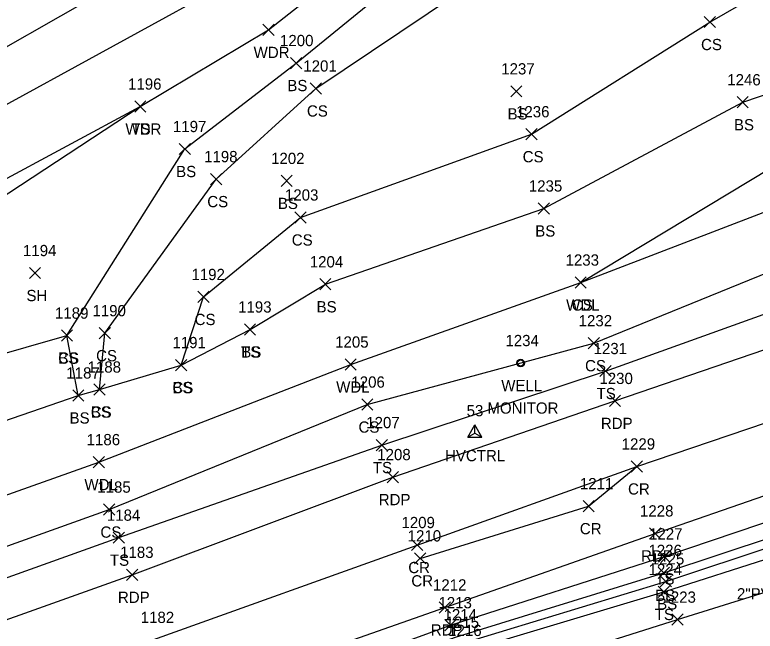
# Model space of a CAD drawing. Extents: x 1443064 to 1445163, y 544063 to 544655.
# Drawn here: x 1443332.1 to 1443463.7, y 544192.7 to 544302.3 of the extents above; entities that cross this region are included whole.
import ezdxf

# ---------------------------------------------------------------- set-up
doc = ezdxf.new("R2010")
doc.units = 0
for name, color, linetype in [('C_A', 7, 'Continuous'), ('C_I', 7, 'Continuous'), ('CPSM', 7, 'Continuous'), ('L_A', 7, 'Continuous'), ('L_C', 7, 'Continuous'), ('L_I', 7, 'Continuous'), ('L_TIC', 7, 'Continuous'), ('LAWA', 7, 'Continuous'), ('LAWE', 7, 'Continuous'), ('LELB', 7, 'Continuous'), ('LFNC', 7, 'Continuous'), ('P_A', 7, 'Continuous'), ('P_I', 7, 'Continuous'), ('P_TIC', 7, 'Continuous'), ('PET', 7, 'Continuous'), ('PRC', 7, 'Continuous'), ('U_A', 7, 'Continuous'), ('U_C', 7, 'Continuous'), ('U_I', 7, 'Continuous'), ('UWW', 7, 'Continuous')]:
    doc.layers.add(name, color=color, linetype=linetype)

msp = doc.modelspace()

# ---------------------------------------------------------------- linework, layer by layer
at = {"layer": 'CPSM'}
for p, q in [((1443412.62, 544227.22), (1443413.87, 544229.39)), ((1443415.12, 544227.22), (1443413.87, 544229.39)), ((1443413.87, 544227.94), (1443413.87, 544229.39)), ((1443412.62, 544227.22), (1443413.87, 544227.94)), ((1443412.62, 544227.22), (1443415.12, 544227.22)), ((1443413.87, 544227.94), (1443413.87, 544227.94)), ((1443413.87, 544227.94), (1443415.12, 544227.22))]:
    msp.add_line(p, q, dxfattribs=at)
at = {"layer": 'L_TIC'}
for points in [[(1443454.64, 544300.02), (1443456.64, 544302.02)], [(1443456.64, 544300.02), (1443454.64, 544302.02)], [(1443376.17, 544298.62), (1443378.17, 544300.62)], [(1443378.17, 544298.62), (1443376.17, 544300.62)], [(1443381.08, 544292.73), (1443383.08, 544294.73)], [(1443383.08, 544292.73), (1443381.08, 544294.73)], [(1443384.57, 544288.21), (1443386.57, 544290.21)], [(1443386.57, 544288.21), (1443384.57, 544290.21)], [(1443420.24, 544287.7), (1443422.24, 544289.7)], [(1443422.24, 544287.7), (1443420.24, 544289.7)], [(1443460.49, 544285.76), (1443462.49, 544287.76)], [(1443462.49, 544285.76), (1443460.49, 544287.76)], [(1443353.38, 544285), (1443355.38, 544287)], [(1443355.38, 544285), (1443353.38, 544287)], [(1443353.38, 544285), (1443355.38, 544287)], [(1443355.38, 544285), (1443353.38, 544287)], [(1443422.93, 544280.08), (1443424.93, 544282.08)], [(1443424.93, 544280.08), (1443422.93, 544282.08)], [(1443361.31, 544277.45), (1443363.31, 544279.45)], [(1443363.31, 544277.45), (1443361.31, 544279.45)], [(1443366.85, 544272.1), (1443368.85, 544274.1)], [(1443368.85, 544272.1), (1443366.85, 544274.1)], [(1443379.4, 544271.78), (1443381.4, 544273.78)], [(1443381.4, 544271.78), (1443379.4, 544273.78)], [(1443425.15, 544266.88), (1443427.15, 544268.88)], [(1443427.15, 544266.88), (1443425.15, 544268.88)], [(1443381.87, 544265.28), (1443383.87, 544267.28)], [(1443383.87, 544265.28), (1443381.87, 544267.28)], [(1443334.65, 544255.4), (1443336.65, 544257.4)], [(1443336.65, 544255.4), (1443334.65, 544257.4)], [(1443386.28, 544253.4), (1443388.28, 544255.4)], [(1443388.28, 544253.4), (1443386.28, 544255.4)], [(1443431.68, 544253.71), (1443433.68, 544255.71)], [(1443433.68, 544253.71), (1443431.68, 544255.71)], [(1443431.68, 544253.71), (1443433.68, 544255.71)], [(1443433.68, 544253.71), (1443431.68, 544255.71)], [(1443364.6, 544251.15), (1443366.6, 544253.15)], [(1443366.6, 544251.15), (1443364.6, 544253.15)], [(1443347.08, 544244.71), (1443349.08, 544246.71)], [(1443349.08, 544244.71), (1443347.08, 544246.71)], [(1443347.08, 544244.71), (1443349.08, 544246.71)], [(1443349.08, 544244.71), (1443347.08, 544246.71)], [(1443372.89, 544245.37), (1443374.89, 544247.37)], [(1443374.89, 544245.37), (1443372.89, 544247.37)], [(1443372.89, 544245.37), (1443374.89, 544247.37)], [(1443374.89, 544245.37), (1443372.89, 544247.37)], [(1443340.34, 544244.28), (1443342.34, 544246.28)], [(1443342.34, 544244.28), (1443340.34, 544246.28)], [(1443340.34, 544244.28), (1443342.34, 544246.28)], [(1443342.34, 544244.28), (1443340.34, 544246.28)], [(1443434.02, 544242.93), (1443436.02, 544244.93)], [(1443436.02, 544242.93), (1443434.02, 544244.93)], [(1443360.65, 544239.04), (1443362.65, 544241.04)], [(1443362.65, 544239.04), (1443360.65, 544241.04)], [(1443360.65, 544239.04), (1443362.65, 544241.04)], [(1443362.65, 544239.04), (1443360.65, 544241.04)], [(1443390.79, 544239.14), (1443392.79, 544241.14)], [(1443392.79, 544239.14), (1443390.79, 544241.14)], [(1443436.1, 544237.98), (1443438.1, 544239.98)], [(1443438.1, 544237.98), (1443436.1, 544239.98)], [(1443346.13, 544234.69), (1443348.13, 544236.69)], [(1443348.13, 544234.69), (1443346.13, 544236.69)], [(1443346.13, 544234.69), (1443348.13, 544236.69)], [(1443348.13, 544234.69), (1443346.13, 544236.69)], [(1443342.36, 544233.64), (1443344.36, 544235.64)], [(1443344.36, 544233.64), (1443342.36, 544235.64)], [(1443342.36, 544233.64), (1443344.36, 544235.64)], [(1443344.36, 544233.64), (1443342.36, 544235.64)], [(1443393.74, 544232.02), (1443395.74, 544234.02)], [(1443395.74, 544232.02), (1443393.74, 544234.02)], [(1443396.32, 544224.82), (1443398.32, 544226.82)], [(1443398.32, 544224.82), (1443396.32, 544226.82)], [(1443346.02, 544221.79), (1443348.02, 544223.79)], [(1443348.02, 544221.79), (1443346.02, 544223.79)], [(1443347.85, 544213.35), (1443349.85, 544215.35)], [(1443349.85, 544213.35), (1443347.85, 544215.35)], [(1443349.56, 544208.36), (1443351.56, 544210.36)], [(1443351.56, 544208.36), (1443349.56, 544210.36)], [(1443446.54, 544205.03), (1443448.54, 544207.03)], [(1443448.54, 544205.03), (1443446.54, 544207.03)], [(1443446.48, 544202.1), (1443448.48, 544204.1)], [(1443448.48, 544202.1), (1443446.48, 544204.1)], [(1443446.84, 544200.59), (1443448.84, 544202.59)], [(1443448.84, 544200.59), (1443446.84, 544202.59)], [(1443446.45, 544198.71), (1443448.45, 544200.71)], [(1443448.45, 544198.71), (1443446.45, 544200.71)], [(1443448.91, 544193.79), (1443450.91, 544195.79)], [(1443450.91, 544193.79), (1443448.91, 544195.79)], [(1443408.52, 544192.8), (1443410.52, 544194.8)], [(1443410.52, 544192.8), (1443408.52, 544194.8)]]:
    msp.add_lwpolyline(points, dxfattribs=at)
at = {"layer": 'LAWA'}
for points in [[(1443328.33, 544272.01), (1443354.38, 544286), (1443377.17, 544299.62), (1443408.35, 544324.23), (1443444.34, 544348.07), (1443478.82, 544379), (1443505.14, 544393.05), (1443523.9, 544408.72), (1443558.4, 544420.46), (1443603.2, 544442.99), (1443623.82, 544449.76), (1443648.97, 544490.11)], [(1443161.29, 544157.23), (1443186.09, 544163.69), (1443194.34, 544166.63), (1443196.33, 544167.63), (1443201.36, 544168), (1443240.97, 544179.17), (1443262.42, 544188.86), (1443303.08, 544207.19), (1443347.02, 544222.79), (1443391.79, 544240.14), (1443432.68, 544254.71), (1443466.61, 544275.19), (1443493.21, 544282.75), (1443512.25, 544287.37), (1443549.07, 544304.36), (1443598.9, 544317.54), (1443643.36, 544329.59), (1443677.18, 544341.83), (1443688.03, 544341.71), (1443709.45, 544338.47), (1443741.32, 544354.61), (1443794.32, 544372.46), (1443818.98, 544380.86)]]:
    msp.add_lwpolyline(points, dxfattribs=at)
at = {"layer": 'LAWE'}
msp.add_lwpolyline([(1443627.73, 544516.96), (1443602.93, 544465.06), (1443560.09, 544445.87), (1443514.11, 544419.1), (1443476.33, 544389.4), (1443439.4, 544357.75), (1443402.97, 544339.11), (1443368.14, 544318.06), (1443323.16, 544292.42), (1443281.44, 544273.46), (1443240.37, 544261.14), (1443193.33, 544260.65), (1443164.34, 544237.83), (1443139.78, 544220.74), (1443138.28, 544217.17), (1443133.77, 544210.32), (1443100.97, 544202.05)], dxfattribs=at)
at = {"layer": 'LELB'}
for points in [[(1443630.6, 544513.66), (1443606.19, 544459.79), (1443563.47, 544440.26), (1443516.58, 544414.23), (1443479.57, 544386.27), (1443441.49, 544354.15), (1443406.03, 544333.57), (1443372.48, 544309.35), (1443326.54, 544284.19), (1443284.74, 544264.48), (1443242.9, 544256.57), (1443195.74, 544252.68), (1443182.88, 544237.49), (1443172.34, 544228.16)], [(1443348.08, 544245.71), (1443367.85, 544273.1), (1443385.57, 544289.21), (1443415.45, 544309.3), (1443446.5, 544327.39), (1443476.22, 544341.09), (1443487.16, 544364.37), (1443505.14, 544393.05)], [(1443343.36, 544234.64), (1443341.34, 544245.28), (1443362.31, 544278.45), (1443382.08, 544293.73), (1443410.77, 544317.09), (1443446.9, 544337.74), (1443471.29, 544351.11), (1443478.82, 544379)], [(1443073.59, 544128.34), (1443116.66, 544141.89), (1443162.8, 544149.75), (1443198.07, 544157.24), (1443242.5, 544173.41), (1443262.84, 544182.05), (1443307.11, 544199.46), (1443348.85, 544214.35), (1443394.74, 544233.02), (1443435.02, 544243.93), (1443473.16, 544259.47), (1443514.32, 544272.16), (1443555.56, 544285.54), (1443605.06, 544302.52), (1443644.56, 544313.72), (1443676.09, 544324.26), (1443689.45, 544326.75), (1443708.55, 544330.01), (1443714.07, 544333.45), (1443742.84, 544349.83), (1443793.92, 544368.99), (1443822.61, 544377.56)], [(1443074.67, 544122.4), (1443120.32, 544131.74), (1443165.11, 544143.77), (1443199.58, 544153.13), (1443245.24, 544167.88), (1443264.59, 544177.57), (1443308.86, 544194.48), (1443350.56, 544209.36), (1443397.32, 544225.82), (1443437.1, 544238.98), (1443476.53, 544253.14), (1443516.75, 544265.8), (1443558.95, 544280.95), (1443607.52, 544296.39), (1443646.45, 544306.32), (1443685.12, 544319.06), (1443714.26, 544329.16), (1443721.31, 544331.26), (1443744.28, 544345.57), (1443795.65, 544366.53), (1443822.61, 544377.56)], [(1443298.3, 544219.12), (1443343.36, 544234.64), (1443347.13, 544235.69), (1443361.65, 544240.04), (1443373.89, 544246.37), (1443387.28, 544254.4), (1443426.15, 544267.88), (1443461.49, 544286.76), (1443487.3, 544295.55), (1443508.64, 544301.52), (1443524.64, 544310.64), (1443543.83, 544318.46), (1443565.18, 544320.82), (1443579.86, 544324.28), (1443590.71, 544328.22), (1443606.37, 544329.69), (1443641.44, 544343.33), (1443674.4, 544354.73), (1443679.77, 544354.99), (1443682.99, 544355.5), (1443689.34, 544351.28), (1443707.83, 544344.95), (1443741.32, 544354.61)], [(1443361.65, 544240.04), (1443365.6, 544252.15), (1443382.87, 544266.28), (1443423.93, 544281.08), (1443455.64, 544301.02), (1443483.09, 544316.84), (1443502.95, 544323.75), (1443492.91, 544341.29), (1443492.61, 544354.67)], [(1443082.68, 544086.51), (1443130.13, 544099.67), (1443144.13, 544104.98), (1443172.72, 544113.76), (1443212.83, 544125.42), (1443253.97, 544138.87), (1443319.39, 544160.76), (1443361, 544176.06), (1443409.52, 544193.8), (1443447.54, 544206.03), (1443485.93, 544218.99), (1443527.17, 544233.73), (1443570.65, 544246.93), (1443621.44, 544264.66), (1443656.15, 544276.08), (1443695.78, 544288.38), (1443720.36, 544296.79), (1443749.28, 544306.83), (1443759.63, 544310.57), (1443806.78, 544328.14), (1443835.8, 544338.24)], [(1443319.92, 544153.98), (1443361.38, 544174.3), (1443410.41, 544191.66), (1443447.48, 544203.1), (1443486.62, 544216.08), (1443527.2, 544231.22), (1443571.34, 544244.18), (1443622.82, 544261.27), (1443656.98, 544272.97), (1443695.69, 544285.56), (1443722.38, 544294.2), (1443748.12, 544301.75), (1443761.69, 544309.21), (1443807.82, 544325.32), (1443837.04, 544335.82)], [(1443432.68, 544254.71), (1443470.23, 544269.11), (1443497.41, 544276.29), (1443512.42, 544282.49), (1443553.95, 544298.49)], [(1443347.34, 544164.94), (1443362.1, 544171.53), (1443410.79, 544190.32), (1443447.84, 544201.59), (1443487.26, 544214.65), (1443527.73, 544229.42), (1443571.89, 544241.52), (1443623.27, 544260), (1443657.62, 544270.44), (1443688.01, 544274.03), (1443701.05, 544275.03), (1443736.1, 544284.41), (1443746.14, 544291.27)], [(1443065.69, 544181.55), (1443109.31, 544188.89), (1443136.73, 544199.63), (1443157.94, 544207.35), (1443161.61, 544194.55), (1443179.72, 544186.99), (1443184.46, 544169.42), (1443186.09, 544163.69), (1443190.43, 544160.91), (1443201.88, 544165.55), (1443201.36, 544168), (1443198.62, 544178.69), (1443186.97, 544194.77), (1443179.33, 544201.28), (1443169.79, 544215.76), (1443186.02, 544215.66), (1443204.39, 544216.66), (1443224.03, 544235.31), (1443250.92, 544228.56), (1443292.51, 544245.42), (1443354.38, 544286)], [(1443261.77, 544197.6), (1443297.02, 544232.6), (1443341.34, 544245.28)], [(1443347.13, 544235.69), (1443348.08, 544245.71)], [(1443347.34, 544164.94), (1443362.66, 544168.7), (1443411.3, 544188.87), (1443447.45, 544199.71), (1443486.7, 544212.27), (1443529.19, 544224.77), (1443545.25, 544228.26), (1443571.88, 544240.98), (1443578.87, 544240.7)]]:
    msp.add_lwpolyline(points, dxfattribs=at)
at = {"layer": 'LFNC'}
msp.add_lwpolyline([(1443239.88, 544119.45), (1443278.62, 544130.94), (1443320.57, 544148.06), (1443338.13, 544157.08), (1443351.22, 544161.82), (1443363.5, 544166.21), (1443412.24, 544182.91), (1443449.91, 544194.79), (1443489.63, 544207.22), (1443534.54, 544218.89), (1443545.24, 544222.13), (1443555.28, 544222.99), (1443566.76, 544221.91), (1443584.49, 544223.6), (1443632.95, 544239.56), (1443668.35, 544248.03), (1443707.08, 544263.81), (1443742.56, 544273.31)], dxfattribs=at)
at = {"layer": 'P_TIC'}
for points in [[(1443437.78, 544232.67), (1443439.78, 544234.67)], [(1443439.78, 544232.67), (1443437.78, 544234.67)], [(1443441.67, 544221.02), (1443443.67, 544223.02)], [(1443443.67, 544221.02), (1443441.67, 544223.02)], [(1443441.67, 544221.02), (1443443.67, 544223.02)], [(1443443.67, 544221.02), (1443441.67, 544223.02)], [(1443398.28, 544219.13), (1443400.28, 544221.13)], [(1443400.28, 544219.13), (1443398.28, 544221.13)], [(1443433.1, 544213.96), (1443435.1, 544215.96)], [(1443435.1, 544213.96), (1443433.1, 544215.96)], [(1443444.92, 544209.12), (1443446.92, 544211.12)], [(1443446.92, 544209.12), (1443444.92, 544211.12)], [(1443402.59, 544207.05), (1443404.59, 544209.05)], [(1443404.59, 544207.05), (1443402.59, 544209.05)], [(1443403.14, 544204.68), (1443405.14, 544206.68)], [(1443405.14, 544204.68), (1443403.14, 544206.68)], [(1443351.92, 544201.76), (1443353.92, 544203.76)], [(1443353.92, 544201.76), (1443351.92, 544203.76)], [(1443407.54, 544195.96), (1443409.54, 544197.96)], [(1443409.54, 544195.96), (1443407.54, 544197.96)]]:
    msp.add_lwpolyline(points, dxfattribs=at)
at = {"layer": 'PET'}
for points in [[(1443075.39, 544117.71), (1443121.41, 544129.24), (1443165.99, 544140.07), (1443200.71, 544149.88), (1443246.42, 544165.39), (1443265.96, 544172.48), (1443311.2, 544187.88), (1443352.92, 544202.76), (1443399.28, 544220.13), (1443438.78, 544233.67), (1443478.75, 544247.35), (1443518.41, 544260.6), (1443561.23, 544274.05), (1443611.7, 544290.5), (1443646.84, 544301.68), (1443684.98, 544314.55), (1443724.57, 544327.54), (1443735.41, 544331.22), (1443748.81, 544336.36), (1443799.43, 544353.96), (1443827.31, 544364.14)], [(1443081.93, 544089.54), (1443128.67, 544104.01), (1443173.03, 544117.15), (1443209.23, 544128.71), (1443253.49, 544142.88), (1443273.3, 544149.07), (1443318.27, 544165.2), (1443359.78, 544179.84), (1443408.54, 544196.96), (1443445.92, 544210.12), (1443484.92, 544223.61), (1443525.67, 544237.02), (1443568.63, 544251.04), (1443620.57, 544267.93), (1443654.52, 544278.93), (1443694.69, 544292.43), (1443717.24, 544299.44), (1443752.8, 544310.97), (1443757.72, 544314.31), (1443805.74, 544330.07), (1443835.35, 544341.18)]]:
    msp.add_lwpolyline(points, dxfattribs=at)
at = {"layer": 'PRC'}
for points in [[(1443078.47, 544103.68), (1443125.02, 544115.93), (1443169.41, 544128.22), (1443204.47, 544139.4), (1443250.36, 544154.3), (1443269.99, 544160.83), (1443315.13, 544176.71), (1443356.58, 544191.19), (1443403.59, 544208.05), (1443442.67, 544222.02), (1443482.15, 544235.41), (1443522.16, 544248.37), (1443565.47, 544262.64), (1443616.51, 544279.34), (1443650.9, 544289.93), (1443689.58, 544302.53), (1443728.44, 544315.77), (1443753.53, 544324.68), (1443803.56, 544342.2), (1443830.96, 544352.16)], [(1443404.14, 544205.68), (1443434.1, 544214.96), (1443442.67, 544222.02)]]:
    msp.add_lwpolyline(points, dxfattribs=at)
at = {"layer": 'UWW'}
for radius in [0.667, 0.625, 0.583, 0.542]:
    msp.add_circle((1443422, 544240.4), radius, dxfattribs=at)

# ---------------------------------------------------------------- texts
at = {"layer": 'C_A'}
msp.add_text('HVCTRL', height=2, dxfattribs=at).set_placement((1443408.56, 544222.94))
at = {"layer": 'C_I'}
msp.add_text('53', height=2, dxfattribs=at).set_placement((1443412.4, 544230.94))
at = {"layer": 'L_A'}
for s, p in [('CS', (1443454.08, 544296.02)), ('WDR', (1443374.53, 544294.62)), ('BS', (1443380.52, 544288.73)), ('CS', (1443384.01, 544284.21)), ('BS', (1443419.68, 544283.7)), ('BS', (1443459.93, 544281.76)), ('WDR', (1443351.74, 544281)), ('TS', (1443352.79, 544281)), ('CS', (1443422.37, 544276.08)), ('BS', (1443360.75, 544273.45)), ('CS', (1443366.29, 544268.1)), ('BS', (1443378.84, 544267.78)), ('BS', (1443424.6, 544262.88)), ('CS', (1443381.31, 544261.28)), ('SH', (1443334.14, 544251.4)), ('BS', (1443385.72, 544249.4)), ('WDL', (1443430.1, 544249.71)), ('CS', (1443431.12, 544249.71)), ('CS', (1443364.04, 544247.15)), ('CS', (1443346.52, 544240.71)), ('CS', (1443346.52, 544240.71)), ('TS', (1443372.3, 544241.37)), ('BS', (1443372.33, 544241.37)), ('CS', (1443339.78, 544240.28)), ('BS', (1443339.78, 544240.28)), ('CS', (1443433.46, 544238.93)), ('CS', (1443360.09, 544235.04)), ('BS', (1443360.09, 544235.04)), ('WDL', (1443389.21, 544235.14)), ('TS', (1443435.51, 544233.98)), ('CS', (1443345.57, 544230.69)), ('BS', (1443345.57, 544230.69)), ('BS', (1443341.8, 544229.64)), ('BS', (1443341.8, 544229.64)), ('CS', (1443393.18, 544228.02)), ('TS', (1443395.73, 544220.82)), ('WDL', (1443344.44, 544217.79)), ('CS', (1443347.29, 544209.35)), ('TS', (1443348.97, 544204.36)), ('TS', (1443445.95, 544201.03)), ('BS', (1443445.92, 544198.1)), ('BS', (1443446.28, 544196.59)), ('TS', (1443445.85, 544194.71))]:
    msp.add_text(s, height=2, dxfattribs=at).set_placement(p)
at = {"layer": 'L_C'}
msp.add_text(' 2"PVC STAND PIPE', height=2, dxfattribs=at).set_placement((1443459.72, 544198.38))
at = {"layer": 'L_I'}
for s, p in [('1200', (1443379.22, 544296.73)), ('1201', (1443383.36, 544292.21)), ('1237', (1443418.55, 544291.7)), ('1246', (1443458.74, 544289.76)), ('1196', (1443352.2, 544289)), ('1196', (1443352.2, 544289)), ('1236', (1443421.19, 544284.08)), ('1197', (1443360.18, 544281.45)), ('1198', (1443365.72, 544276.1)), ('1202', (1443377.63, 544275.78)), ('1235', (1443423.46, 544270.88)), ('1203', (1443380.1, 544269.28)), ('1194', (1443333.52, 544259.4)), ('1233', (1443429.99, 544257.71)), ('1233', (1443429.99, 544257.71)), ('1204', (1443384.51, 544257.4)), ('1192', (1443363.47, 544255.15)), ('1190', (1443345.87, 544248.71)), ('1190', (1443345.87, 544248.71)), ('1193', (1443371.77, 544249.37)), ('1193', (1443371.77, 544249.37)), ('1189', (1443339.21, 544248.28)), ('1189', (1443339.21, 544248.28)), ('1232', (1443432.32, 544246.93)), ('1191', (1443360.09, 544243.04)), ('1191', (1443360.09, 544243.04)), ('1205', (1443389.02, 544243.14)), ('1231', (1443434.97, 544241.98)), ('1188', (1443345, 544238.69)), ('1188', (1443345, 544238.69)), ('1187', (1443341.23, 544237.64)), ('1187', (1443341.23, 544237.64)), ('1206', (1443391.91, 544236.02)), ('1207', (1443394.55, 544228.82)), ('1186', (1443344.84, 544225.79)), ('1185', (1443346.73, 544217.35)), ('1184', (1443348.43, 544212.36)), ('1227', (1443444.84, 544209.03)), ('1226', (1443444.73, 544206.1)), ('1225', (1443445.15, 544204.59)), ('1224', (1443444.75, 544202.71)), ('1223', (1443447.22, 544197.79)), ('1213', (1443407.39, 544196.8)), ('1214', (1443408.29, 544194.66)), ('1215', (1443408.67, 544193.32)), ('1216', (1443409.12, 544191.87))]:
    msp.add_text(s, height=2, dxfattribs=at).set_placement(p)
at = {"layer": 'P_A'}
for s, p in [('RDP', (1443436.27, 544228.67)), ('CR', (1443441.1, 544217.02)), ('CR', (1443441.1, 544217.02)), ('RDP', (1443396.77, 544215.13)), ('CR', (1443432.53, 544209.96)), ('RDP', (1443443.41, 544205.12)), ('CR', (1443402.03, 544203.05)), ('CR', (1443402.57, 544200.68)), ('RDP', (1443350.4, 544197.76)), ('RDP', (1443406.03, 544191.96))]:
    msp.add_text(s, height=2, dxfattribs=at).set_placement(p)
at = {"layer": 'P_I'}
for s, p in [('1230', (1443436.01, 544236.67)), ('1229', (1443439.97, 544225.02)), ('1229', (1443439.97, 544225.02)), ('1208', (1443396.51, 544223.13)), ('1211', (1443432.54, 544217.96)), ('1228', (1443443.23, 544213.12)), ('1209', (1443400.81, 544211.05)), ('1210', (1443401.92, 544208.68)), ('1183', (1443350.79, 544205.76)), ('1212', (1443406.42, 544199.96)), ('1182', (1443354.45, 544194.19))]:
    msp.add_text(s, height=2, dxfattribs=at).set_placement(p)
at = {"layer": 'U_A'}
msp.add_text('WELL', height=2, dxfattribs=at).set_placement((1443418.56, 544235.4))
at = {"layer": 'U_C'}
msp.add_text('MONITOR', height=2, dxfattribs=at).set_placement((1443416.1, 544231.4))
at = {"layer": 'U_I'}
msp.add_text('1234', height=2, dxfattribs=at).set_placement((1443419.3, 544243.4))

doc.saveas('drawing.dxf')
